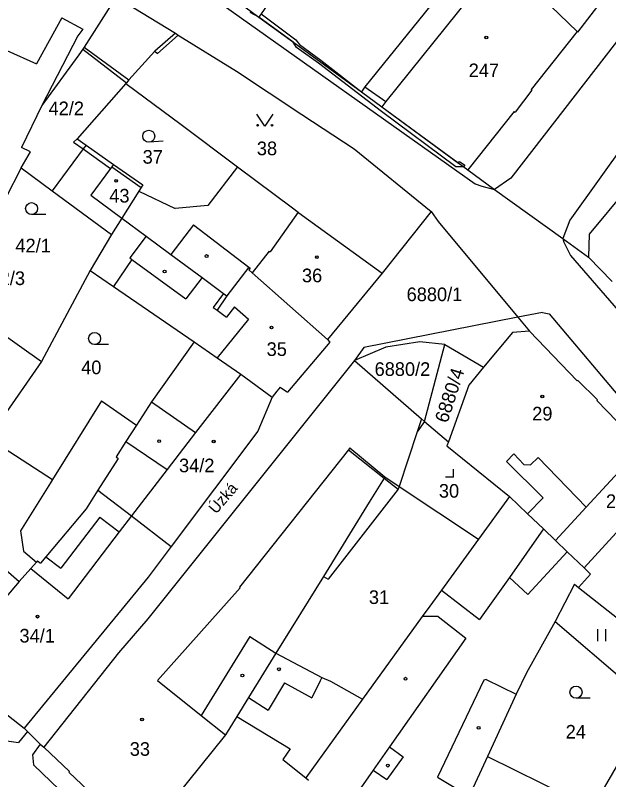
# Model space of a CAD drawing. Extents: x -593183 to -588034, y -1130415 to -1124994.
# Drawn here: x -590895.3 to -590821.2, y -1128791.9 to -1128696.5 of the extents above; entities that cross this region are included whole.
import ezdxf

# ---------------------------------------------------------------- set-up
doc = ezdxf.new("R2010")
doc.units = 0
for name, color, linetype in [('Vrstva 1', 7, 'Continuous'), ('Vrstva 15', 7, 'Continuous'), ('Vrstva 16', 7, 'Continuous'), ('Vrstva 18', 7, 'Continuous'), ('Vrstva 19', 7, 'Continuous'), ('Vrstva 25', 7, 'Continuous'), ('Vrstva 27', 7, 'Continuous'), ('Vrstva 4', 7, 'Continuous')]:
    doc.layers.add(name, color=color, linetype=linetype)

msp = doc.modelspace()

# ---------------------------------------------------------------- linework, layer by layer
at = {"layer": 'Vrstva 1'}
for p, q in [((-590804.12, -1128678.96), (-590833.39, -1128716.78)), ((-590795.08, -1128678.56), (-590826.02, -1128722.06)), ((-590884.82, -1128684.14), (-590837.88, -1128717.49)), ((-590834.54, -1128689.37), (-590825.14, -1128698.51)), ((-590818.46, -1128689.99), (-590825.08, -1128698.56)), ((-590871.54, -1128691.75), (-590864.88, -1128696.7)), ((-590882.69, -1128694.18), (-590886.7, -1128700.44)), ((-590882.69, -1128694.18), (-590875.29, -1128698.7)), ((-590889.48, -1128696.77), (-590892.64, -1128702.51)), ((-590889.48, -1128696.77), (-590886.86, -1128698.22)), ((-590864.88, -1128696.7), (-590859.77, -1128700.42)), ((-590886.86, -1128698.22), (-590887.48, -1128699.03)), ((-590887.48, -1128699.03), (-590891.99, -1128707.71)), ((-590875.29, -1128698.7), (-590877.88, -1128700.96)), ((-590875.29, -1128698.7), (-590874.94, -1128698.93)), ((-590874.94, -1128698.93), (-590867.68, -1128703.45)), ((-590825.14, -1128698.51), (-590830.86, -1128705.74)), ((-590825.14, -1128698.51), (-590825.08, -1128698.56)), ((-590896.36, -1128700.87), (-590892.64, -1128702.51)), ((-590886.86, -1128700.69), (-590887.33, -1128701.42)), ((-590886.7, -1128700.44), (-590886.86, -1128700.69)), ((-590877.88, -1128700.96), (-590881.1, -1128704.54)), ((-590859.77, -1128700.42), (-590852.06, -1128706.01)), ((-590887.33, -1128701.42), (-590891.99, -1128707.71)), ((-590867.68, -1128703.45), (-590859.5, -1128708.84)), ((-590881.48, -1128704.97), (-590887.57, -1128711.87)), ((-590881.4, -1128704.88), (-590881.48, -1128704.97)), ((-590881.48, -1128704.97), (-590874.57, -1128710.08)), ((-590881.1, -1128704.54), (-590881.4, -1128704.88)), ((-590851.64, -1128705.38), (-590852.06, -1128706.01)), ((-590851.64, -1128705.38), (-590849.02, -1128707.21)), ((-590830.78, -1128705.8), (-590832.88, -1128708.55)), ((-590830.86, -1128705.74), (-590830.78, -1128705.8)), ((-590891.99, -1128707.71), (-590894.5, -1128712.99)), ((-590849.02, -1128707.21), (-590849.5, -1128707.91)), ((-590849.5, -1128707.91), (-590838.77, -1128715.77)), ((-590859.5, -1128708.84), (-590852.98, -1128713.14)), ((-590832.98, -1128708.47), (-590838.77, -1128715.77)), ((-590832.98, -1128708.47), (-590832.88, -1128708.55)), ((-590874.57, -1128710.08), (-590867.52, -1128715.38)), ((-590813.27, -1128711.28), (-590823.64, -1128723.78)), ((-590887.57, -1128711.87), (-590886.43, -1128712.67)), ((-590886.43, -1128712.67), (-590886.79, -1128713.15)), ((-590886.43, -1128712.67), (-590883.01, -1128715.08)), ((-590894.56, -1128715.49), (-590893.38, -1128713.5)), ((-590893.38, -1128713.5), (-590894.5, -1128712.99)), ((-590886.79, -1128713.15), (-590890.66, -1128718.37)), ((-590852.98, -1128713.14), (-590843.34, -1128720.96)), ((-590894.56, -1128715.49), (-590896.49, -1128719.35)), ((-590894.56, -1128715.49), (-590890.66, -1128718.37)), ((-590883.01, -1128715.08), (-590879.36, -1128717.65)), ((-590867.52, -1128715.38), (-590871.25, -1128720.21)), ((-590867.52, -1128715.38), (-590860.69, -1128720.52)), ((-590838.77, -1128715.77), (-590835.43, -1128718.2)), ((-590833.39, -1128716.78), (-590835.43, -1128718.2)), ((-590890.66, -1128718.37), (-590883.26, -1128723.82)), ((-590879.84, -1128718.41), (-590882, -1128721.79)), ((-590879.55, -1128717.95), (-590879.84, -1128718.41)), ((-590879.84, -1128718.41), (-590875.31, -1128720.58)), ((-590879.36, -1128717.65), (-590879.55, -1128717.95)), ((-590837.88, -1128717.49), (-590837.01, -1128717.78)), ((-590837.01, -1128717.78), (-590835.43, -1128718.2)), ((-590835.43, -1128718.2), (-590826.93, -1128724.31)), ((-590871.25, -1128720.21), (-590875.31, -1128720.58)), ((-590860.69, -1128720.52), (-590859.98, -1128721.06)), ((-590859.98, -1128721.06), (-590859.87, -1128721.14)), ((-590859.87, -1128721.14), (-590849.47, -1128728.66)), ((-590843.34, -1128720.96), (-590849.47, -1128728.66)), ((-590843.34, -1128720.96), (-590842.5, -1128722.22)), ((-590882, -1128721.79), (-590883.26, -1128723.82)), ((-590882, -1128721.79), (-590878.93, -1128724.05)), ((-590842.5, -1128722.22), (-590832.52, -1128734.15)), ((-590826.02, -1128722.06), (-590826.93, -1128724.31)), ((-590883.26, -1128723.82), (-590885.92, -1128728.34)), ((-590878.93, -1128724.05), (-590875.87, -1128726.31)), ((-590823.64, -1128723.78), (-590823.69, -1128726.65)), ((-590826.93, -1128724.31), (-590826.8, -1128724.77)), ((-590826.93, -1128724.31), (-590823.69, -1128726.65)), ((-590826.8, -1128724.77), (-590825.94, -1128726.46)), ((-590875.87, -1128726.31), (-590871.97, -1128729.19)), ((-590825.94, -1128726.46), (-590791.35, -1128766.62)), ((-590823.69, -1128726.65), (-590820.76, -1128729.7)), ((-590866.12, -1128727.9), (-590868.86, -1128731.48)), ((-590866.12, -1128727.9), (-590865.96, -1128728.02)), ((-590885.92, -1128728.34), (-590892.03, -1128739.69)), ((-590885.92, -1128728.34), (-590883.04, -1128730.32)), ((-590865.96, -1128728.02), (-590866.12, -1128728.23)), ((-590866.12, -1128728.23), (-590865.69, -1128728.61)), ((-590865.69, -1128728.61), (-590856.3, -1128736.93)), ((-590849.47, -1128728.66), (-590856.3, -1128736.93)), ((-590871.97, -1128729.19), (-590869.27, -1128731.18)), ((-590883.04, -1128730.32), (-590872.95, -1128737.23)), ((-590869.27, -1128731.18), (-590868.86, -1128731.48)), ((-590900.45, -1128733.67), (-590892.03, -1128739.69)), ((-590829.46, -1128733.55), (-590832.52, -1128734.15)), ((-590829.46, -1128733.55), (-590828.62, -1128733.75)), ((-590832.52, -1128734.15), (-590831.06, -1128735.9)), ((-590828.62, -1128733.75), (-590785.59, -1128784.71)), ((-590833.21, -1128736.05), (-590836.8, -1128740.4)), ((-590831.06, -1128735.9), (-590833.21, -1128736.05)), ((-590831.06, -1128735.9), (-590825.11, -1128742.11)), ((-590872.95, -1128737.23), (-590878.27, -1128744.73)), ((-590872.95, -1128737.23), (-590870.08, -1128739.23)), ((-590856, -1128737.28), (-590861.29, -1128743.52)), ((-590856.3, -1128736.93), (-590856, -1128737.28)), ((-590844.78, -1128737.22), (-590849.02, -1128737.9)), ((-590841.65, -1128737.56), (-590844.78, -1128737.22)), ((-590849.02, -1128737.9), (-590852.94, -1128739.56)), ((-590844.18, -1128747.19), (-590841.65, -1128737.56)), ((-590841.65, -1128737.56), (-590836.8, -1128740.4)), ((-590870.08, -1128739.23), (-590867.14, -1128741.27)), ((-590892.03, -1128739.69), (-590897.22, -1128747.12)), ((-590852.94, -1128739.56), (-590878.74, -1128771.82)), ((-590852.94, -1128739.56), (-590844.57, -1128746.85)), ((-590867.14, -1128741.27), (-590863.19, -1128744.15)), ((-590836.8, -1128740.4), (-590838.64, -1128742.64)), ((-590825.03, -1128742.05), (-590825.11, -1128742.11)), ((-590825.03, -1128742.05), (-590822.6, -1128744.48)), ((-590862.23, -1128742.89), (-590862.61, -1128743.39)), ((-590862.23, -1128742.89), (-590861.29, -1128743.52)), ((-590838.64, -1128742.64), (-590841.21, -1128749.73)), ((-590863.19, -1128744.15), (-590865.01, -1128748.36)), ((-590862.61, -1128743.39), (-590863.19, -1128744.15)), ((-590884.52, -1128744.61), (-590890.64, -1128754.42)), ((-590884.52, -1128744.61), (-590880.14, -1128747.63)), ((-590878.27, -1128744.73), (-590880.14, -1128747.63)), ((-590822.6, -1128744.48), (-590822.67, -1128744.55)), ((-590822.67, -1128744.55), (-590817.09, -1128750.37)), ((-590844.57, -1128746.85), (-590844.18, -1128747.19)), ((-590880.14, -1128747.63), (-590881.46, -1128749.67)), ((-590844.18, -1128747.19), (-590845.1, -1128748.48)), ((-590844.18, -1128747.19), (-590841.21, -1128749.73)), ((-590865.01, -1128748.36), (-590875.8, -1128762.76)), ((-590845.1, -1128748.48), (-590847.34, -1128755.27)), ((-590897.97, -1128749.68), (-590890.64, -1128754.42)), ((-590881.46, -1128749.67), (-590882.7, -1128751.6)), ((-590841.21, -1128749.73), (-590841.38, -1128750.21)), ((-590841.38, -1128750.21), (-590833.59, -1128756.54)), ((-590817.46, -1128750.78), (-590823.98, -1128757.86)), ((-590882.45, -1128751.79), (-590884.97, -1128755.76)), ((-590882.7, -1128751.6), (-590882.45, -1128751.79)), ((-590849.21, -1128754.24), (-590851.08, -1128757.26)), ((-590849.12, -1128754.09), (-590849.21, -1128754.24)), ((-590849.12, -1128754.09), (-590847.34, -1128755.27)), ((-590814.23, -1128754.4), (-590824.26, -1128765.45)), ((-590847.34, -1128755.27), (-590837.44, -1128761.84)), ((-590884.97, -1128755.76), (-590886.44, -1128758.08)), ((-590884.97, -1128755.76), (-590880.79, -1128758.95)), ((-590833.59, -1128756.54), (-590837.44, -1128761.84)), ((-590833.59, -1128756.54), (-590831.34, -1128758.69)), ((-590851.08, -1128757.26), (-590856.81, -1128766.5)), ((-590886.44, -1128758.08), (-590891.45, -1128764.07)), ((-590823.98, -1128757.86), (-590827.82, -1128762.04)), ((-590880.79, -1128758.95), (-590875.8, -1128762.76)), ((-590831.34, -1128758.69), (-590829.34, -1128760.59)), ((-590829.34, -1128760.59), (-590827.82, -1128762.04)), ((-590837.44, -1128761.84), (-590842.08, -1128768.23)), ((-590827.82, -1128762.04), (-590826.38, -1128763.43)), ((-590875.8, -1128762.76), (-590878.68, -1128766.61)), ((-590891.45, -1128764.07), (-590892.13, -1128764.84)), ((-590826.38, -1128763.43), (-590824.26, -1128765.45)), ((-590892.63, -1128764.73), (-590893.35, -1128765.53)), ((-590892.49, -1128764.57), (-590892.63, -1128764.73)), ((-590892.49, -1128764.57), (-590892.13, -1128764.84)), ((-590893.35, -1128765.53), (-590894.79, -1128767.13)), ((-590824.26, -1128765.45), (-590824.12, -1128765.58)), ((-590824.12, -1128765.58), (-590823.45, -1128766.24)), ((-590878.68, -1128766.61), (-590894.17, -1128785.44)), ((-590856.81, -1128766.5), (-590862.74, -1128776.07)), ((-590823.45, -1128766.24), (-590824.94, -1128767.88)), ((-590894.79, -1128767.13), (-590903.96, -1128777.88)), ((-590825.46, -1128767.49), (-590827.88, -1128772.12)), ((-590825.46, -1128767.49), (-590824.94, -1128767.88)), ((-590824.94, -1128767.88), (-590813.65, -1128776.8)), ((-590842.08, -1128768.23), (-590843.52, -1128770.21)), ((-590843.52, -1128770.21), (-590844.46, -1128771.5)), ((-590878.74, -1128771.82), (-590882.38, -1128776.05)), ((-590844.46, -1128771.5), (-590851.91, -1128781.83)), ((-590827.88, -1128772.12), (-590831.44, -1128778.53)), ((-590827.88, -1128772.12), (-590815.53, -1128782.75)), ((-590882.38, -1128776.05), (-590891.72, -1128787.81)), ((-590862.74, -1128776.07), (-590866.16, -1128781.61)), ((-590862.74, -1128776.07), (-590857, -1128779.12)), ((-590903.96, -1128777.88), (-590894.17, -1128785.44)), ((-590857, -1128779.12), (-590855.94, -1128779.59)), ((-590831.44, -1128778.53), (-590832.76, -1128781.22)), ((-590855.94, -1128779.59), (-590851.91, -1128781.83)), ((-590832.76, -1128781.22), (-590836.32, -1128789)), ((-590866.16, -1128781.61), (-590867.62, -1128783.99)), ((-590851.91, -1128781.83), (-590859, -1128791.64)), ((-590867.62, -1128783.99), (-590869.04, -1128786.29)), ((-590817.21, -1128785.02), (-590823.42, -1128795.69)), ((-590894.17, -1128785.44), (-590893.75, -1128785.85)), ((-590893.75, -1128785.85), (-590892.16, -1128787.43)), ((-590869.04, -1128786.29), (-590879.52, -1128799.28)), ((-590892.16, -1128787.43), (-590891.72, -1128787.81)), ((-590891.72, -1128787.81), (-590888.5, -1128790.85)), ((-590836.32, -1128789), (-590838.59, -1128793.95)), ((-590836.32, -1128789), (-590826.19, -1128793.96)), ((-590888.5, -1128790.85), (-590888.61, -1128790.95)), ((-590888.61, -1128790.95), (-590885.39, -1128793.99)), ((-590859, -1128791.64), (-590858.66, -1128791.93))]:
    msp.add_line(p, q, dxfattribs=at)
at = {"layer": 'Vrstva 25'}
for p, q in [((-590876.824, -1128712.198), (-590878.57, -1128712.31)), ((-590891.49, -1128721.35), (-590893.24, -1128721.35)), ((-590883.63, -1128737.56), (-590885.38, -1128737.56)), ((-590840.55, -1128754.13), (-590840.55, -1128753.13)), ((-590840.55, -1128754.13), (-590841.55, -1128754.13)), ((-590822.567, -1128773.075), (-590822.567, -1128774.575)), ((-590821.545, -1128774.575), (-590821.545, -1128773.075)), ((-590823.52, -1128781.71), (-590825.27, -1128781.71))]:
    msp.add_line(p, q, dxfattribs=at)
msp.add_lwpolyline([(-590863.13, -1128708.79), (-590864.13, -1128710.29), (-590865.13, -1128708.79)], dxfattribs=at)
for centre, radius in [((-590836.47, -1128699.24), 0.175), ((-590836.47, -1128699.24), 0.15), ((-590865.03, -1128710.19), 0.1), ((-590863.23, -1128710.19), 0.1), ((-590878.618, -1128711.562), 0.75), ((-590882.7, -1128717.14), 0.175), ((-590882.7, -1128717.14), 0.15), ((-590893.24, -1128720.6), 0.75), ((-590871.39, -1128726.52), 0.175), ((-590857.62, -1128726.65), 0.175), ((-590857.62, -1128726.65), 0.15), ((-590876.64, -1128728.44), 0.175), ((-590863.28, -1128735.44), 0.175), ((-590863.28, -1128735.44), 0.15), ((-590885.38, -1128736.81), 0.75), ((-590829.48, -1128744.06), 0.175), ((-590829.48, -1128744.06), 0.15), ((-590877.32, -1128749.62), 0.175), ((-590870.51, -1128749.66), 0.175), ((-590870.51, -1128749.66), 0.15), ((-590892.5, -1128771.53), 0.175), ((-590892.5, -1128771.53), 0.15), ((-590862.36, -1128778.1), 0.175), ((-590866.93, -1128778.88), 0.175), ((-590846.56, -1128779.28), 0.175), ((-590825.27, -1128780.96), 0.75), ((-590879.46, -1128784.37), 0.175), ((-590879.46, -1128784.37), 0.15), ((-590837.43, -1128785.41), 0.175), ((-590848.76, -1128790.13), 0.175)]:
    msp.add_circle(centre, radius, dxfattribs=at)
at = {"layer": 'Vrstva 27'}
for p, q in [((-590864.88, -1128696.7), (-590865.97, -1128696.14)), ((-590864.58, -1128696.27), (-590860.26, -1128699.53)), ((-590860.58, -1128699.83), (-590864.88, -1128696.7)), ((-590860.17, -1128700.47), (-590860.58, -1128699.83)), ((-590860.26, -1128699.53), (-590859.81, -1128700.11)), ((-590859.81, -1128700.11), (-590857.14, -1128702.06)), ((-590857.44, -1128702.46), (-590860.17, -1128700.47)), ((-590857.14, -1128702.06), (-590852.06, -1128706.01)), ((-590849.57, -1128708.49), (-590857.44, -1128702.46)), ((-590852.06, -1128706.01), (-590849.5, -1128707.91)), ((-590849.5, -1128707.91), (-590839.95, -1128714.91)), ((-590840.28, -1128715.37), (-590849.57, -1128708.49)), ((-590839.3, -1128715.38), (-590840.28, -1128715.37)), ((-590839.95, -1128714.91), (-590839.81, -1128714.72)), ((-590839.81, -1128714.72), (-590839.17, -1128715.19)), ((-590839.17, -1128715.19), (-590839.3, -1128715.38))]:
    msp.add_line(p, q, dxfattribs=at)
at = {"layer": 'Vrstva 4'}
for p, q in [((-590857.82, -1128686.53), (-590864.88, -1128696.7)), ((-590838.4, -1128688.97), (-590851.64, -1128705.38)), ((-590835.93, -1128690.96), (-590849.02, -1128707.21)), ((-590874.94, -1128698.93), (-590877.51, -1128701.23)), ((-590886.86, -1128700.69), (-590881.4, -1128704.88)), ((-590886.7, -1128700.44), (-590881.1, -1128704.54)), ((-590877.88, -1128700.96), (-590877.51, -1128701.23)), ((-590887.57, -1128711.87), (-590888.01, -1128712.3)), ((-590888.01, -1128712.3), (-590886.79, -1128713.15)), ((-590886.79, -1128713.15), (-590883.38, -1128715.59)), ((-590883.22, -1128715.37), (-590883.38, -1128715.59)), ((-590883.01, -1128715.08), (-590883.22, -1128715.37)), ((-590883.22, -1128715.37), (-590879.55, -1128717.95)), ((-590883.38, -1128715.59), (-590885.84, -1128718.93)), ((-590885.84, -1128718.93), (-590882, -1128721.79)), ((-590859.98, -1128721.06), (-590863.47, -1128726.01)), ((-590873.03, -1128722.63), (-590875.87, -1128726.31)), ((-590873.03, -1128722.63), (-590866.12, -1128727.9)), ((-590878.93, -1128724.05), (-590881, -1128726.75)), ((-590863.6, -1128725.93), (-590865.69, -1128728.61)), ((-590863.6, -1128725.93), (-590863.47, -1128726.01)), ((-590880.74, -1128726.94), (-590883.04, -1128730.32)), ((-590881, -1128726.75), (-590880.74, -1128726.94)), ((-590880.74, -1128726.94), (-590873.99, -1128731.86)), ((-590871.97, -1128729.19), (-590873.99, -1128731.86)), ((-590869.27, -1128731.18), (-590870.56, -1128732.94)), ((-590868.86, -1128731.48), (-590870.08, -1128733.26)), ((-590870.56, -1128732.94), (-590870.08, -1128733.26)), ((-590870.08, -1128733.26), (-590868.92, -1128734.13)), ((-590867.92, -1128732.85), (-590868.92, -1128734.13)), ((-590867.92, -1128732.85), (-590866.16, -1128734.38)), ((-590866.16, -1128734.38), (-590870.08, -1128739.23)), ((-590832.52, -1128734.15), (-590851.77, -1128737.93)), ((-590851.77, -1128737.93), (-590852.94, -1128739.56)), ((-590867.14, -1128741.27), (-590872.78, -1128748.53)), ((-590878.27, -1128744.73), (-590872.78, -1128748.53)), ((-590844.57, -1128746.85), (-590845.1, -1128748.48)), ((-590872.78, -1128748.53), (-590876.34, -1128753.18)), ((-590881.46, -1128749.67), (-590876.34, -1128753.18)), ((-590853.69, -1128750.69), (-590867.29, -1128767.84)), ((-590853.5, -1128750.45), (-590853.69, -1128750.69)), ((-590853.69, -1128750.69), (-590849.21, -1128754.24)), ((-590853.5, -1128750.45), (-590849.12, -1128754.09)), ((-590833.03, -1128751.22), (-590833.95, -1128752.15)), ((-590833.03, -1128751.22), (-590831.79, -1128752.52)), ((-590830, -1128751.68), (-590830.97, -1128752.57)), ((-590830, -1128751.68), (-590823.98, -1128757.86)), ((-590833.95, -1128752.15), (-590829.37, -1128756.7)), ((-590831.79, -1128752.52), (-590830.97, -1128752.57)), ((-590876.34, -1128753.18), (-590880.79, -1128758.95)), ((-590890.64, -1128754.42), (-590890.9, -1128754.84)), ((-590849.21, -1128754.24), (-590847.46, -1128755.63)), ((-590890.9, -1128754.84), (-590894.64, -1128760.83)), ((-590847.34, -1128755.27), (-590847.46, -1128755.63)), ((-590847.46, -1128755.63), (-590856.21, -1128766.86)), ((-590829.37, -1128756.7), (-590831.34, -1128758.69)), ((-590884.73, -1128759.1), (-590889.58, -1128765.49)), ((-590884.73, -1128759.1), (-590882.3, -1128760.95)), ((-590880.79, -1128758.95), (-590882.3, -1128760.95)), ((-590894.64, -1128760.83), (-590894.26, -1128763.37)), ((-590882.3, -1128760.95), (-590888.67, -1128769.3)), ((-590829.34, -1128760.59), (-590833.58, -1128766.65)), ((-590899.35, -1128763.22), (-590894.79, -1128767.13)), ((-590894.26, -1128763.37), (-590892.63, -1128764.73)), ((-590891.45, -1128764.07), (-590889.58, -1128765.49)), ((-590826.38, -1128763.43), (-590831.27, -1128768.77)), ((-590893.35, -1128765.53), (-590888.67, -1128769.3)), ((-590856.81, -1128766.5), (-590856.21, -1128766.86)), ((-590833.58, -1128766.65), (-590837.34, -1128771.87)), ((-590833.58, -1128766.65), (-590831.27, -1128768.77)), ((-590867.19, -1128767.93), (-590877.52, -1128779.5)), ((-590867.29, -1128767.84), (-590867.19, -1128767.93)), ((-590842.08, -1128768.23), (-590837.34, -1128771.87)), ((-590842.5, -1128771.5), (-590844.46, -1128771.5)), ((-590842.5, -1128771.5), (-590839.03, -1128774.22)), ((-590865.99, -1128774.02), (-590872.07, -1128783.87)), ((-590865.99, -1128774.02), (-590862.74, -1128776.07)), ((-590839.03, -1128774.22), (-590848.56, -1128787.8)), ((-590857, -1128779.12), (-590857.21, -1128779.54)), ((-590836.78, -1128779.46), (-590842.57, -1128791.55)), ((-590836.5, -1128779.39), (-590836.78, -1128779.46)), ((-590836.5, -1128779.39), (-590832.76, -1128781.22)), ((-590877.52, -1128779.5), (-590872.07, -1128783.87)), ((-590861.68, -1128779.81), (-590863.72, -1128783.2)), ((-590861.68, -1128779.81), (-590858.27, -1128781.66)), ((-590857.21, -1128779.54), (-590858.27, -1128781.66)), ((-590866.16, -1128781.61), (-590863.72, -1128783.2)), ((-590872.07, -1128783.87), (-590869.04, -1128786.29)), ((-590867.62, -1128783.99), (-590860.98, -1128788.01)), ((-590893.75, -1128785.85), (-590894.89, -1128787.23)), ((-590896.35, -1128787.05), (-590894.89, -1128787.23)), ((-590892.16, -1128787.43), (-590893.12, -1128788.76)), ((-590860.98, -1128788.01), (-590861.88, -1128789.35)), ((-590848.56, -1128787.8), (-590850.59, -1128790.69)), ((-590848.56, -1128787.8), (-590846.86, -1128789.05)), ((-590893.12, -1128788.76), (-590893, -1128790.01)), ((-590861.88, -1128789.35), (-590859, -1128791.64)), ((-590846.86, -1128789.05), (-590848.87, -1128791.84)), ((-590893, -1128790.01), (-590858.79, -1128822.97)), ((-590850.59, -1128790.69), (-590856.8, -1128799.53)), ((-590850.59, -1128790.69), (-590848.87, -1128791.84)), ((-590842.57, -1128791.55), (-590838.59, -1128793.95))]:
    msp.add_line(p, q, dxfattribs=at)

# ---------------------------------------------------------------- texts
at = {"layer": 'Vrstva 15'}
msp.add_text('Úzká', height=1.4, rotation=49.29372, dxfattribs=at).set_placement((-590870.21, -1128758.8))
at = {"layer": 'Vrstva 16'}
msp.add_text('42/3', height=1.7, dxfattribs=at).set_placement((-590898.49, -1128730.14))
at = {"layer": 'Vrstva 18'}
for s, p in [('42/2', (-590891.13, -1128708.94)), ('38', (-590865.12, -1128713.93)), ('37', (-590879.38, -1128714.99)), ('42/1', (-590895.27, -1128726.06)), ('6880/1', (-590846.42, -1128732.15)), ('40', (-590887.06, -1128741.27)), ('6880/2', (-590850.42, -1128741.48)), ('28', (-590821.53, -1128757.97)), ('31', (-590851.13, -1128769.95)), ('24', (-590826.56, -1128786.75))]:
    msp.add_text(s, height=1.7, dxfattribs=at).set_placement(p)
msp.add_text('6880/4', height=1.7, rotation=71.97732, dxfattribs=at).set_placement((-590841.329, -1128747.459))
at = {"layer": 'Vrstva 19'}
for s, p in [('247', (-590838.67, -1128704.19)), ('43', (-590883.55, -1128719.84)), ('36', (-590859.49, -1128729.79)), ('35', (-590863.9, -1128738.99)), ('29', (-590830.74, -1128747.04)), ('34/2', (-590874.84, -1128753.51)), ('30', (-590842.39, -1128756.68)), ('34/1', (-590894.76, -1128774.76)), ('33', (-590880.99, -1128788.9))]:
    msp.add_text(s, height=1.7, dxfattribs=at).set_placement(p)

doc.saveas('drawing.dxf')
